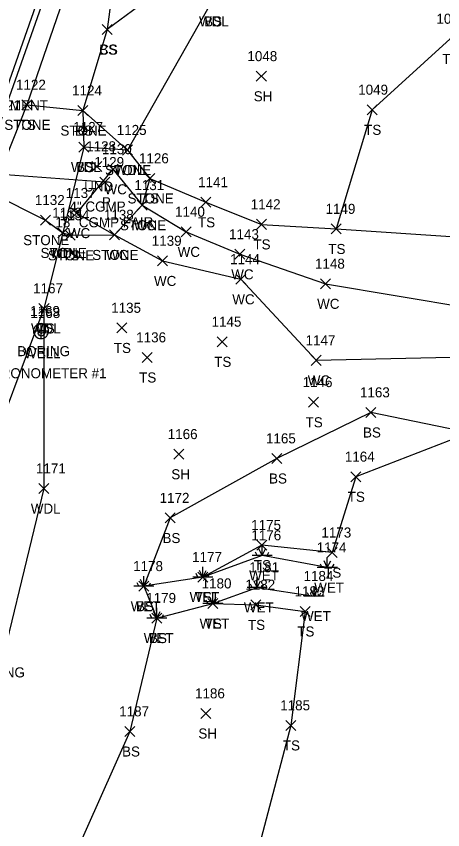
# Model space of a CAD drawing. Extents: x 1551995 to 1555700, y 777276 to 783130.
# Drawn here: x 1554961.7 to 1555046.7, y 777956 to 778118.1 of the extents above; entities that cross this region are included whole.
import ezdxf

# ---------------------------------------------------------------- set-up
doc = ezdxf.new("R2010")
doc.units = 0
for name, color, linetype in [('D_A', 7, 'Continuous'), ('D_C', 7, 'Continuous'), ('D_I', 7, 'Continuous'), ('D_TIC', 7, 'Continuous'), ('DCP', 7, 'Continuous'), ('G_A', 7, 'Continuous'), ('G_I', 7, 'Continuous'), ('GA_P', 7, 'Continuous'), ('L_A', 7, 'Continuous'), ('L_C', 7, 'Continuous'), ('L_I', 7, 'Continuous'), ('L_TIC', 7, 'Continuous'), ('LASF', 7, 'Continuous'), ('LAWA', 7, 'Continuous'), ('LAWE', 7, 'Continuous'), ('LELB', 7, 'Continuous'), ('LWET', 7, 'Continuous'), ('PET', 7, 'Continuous'), ('R_I', 7, 'Continuous'), ('RGR', 7, 'Continuous'), ('U_A', 7, 'Continuous'), ('U_C', 7, 'Continuous'), ('U_I', 7, 'Continuous'), ('UWW', 7, 'Continuous')]:
    doc.layers.add(name, color=color, linetype=linetype)

msp = doc.modelspace()

# ---------------------------------------------------------------- linework, layer by layer
at = {"layer": 'D_TIC'}
for points in [[(1554976.76, 778087.18), (1554978.76, 778089.18)], [(1554978.76, 778087.18), (1554976.76, 778089.18)], [(1554978.38, 778084.04), (1554980.38, 778086.04)], [(1554980.38, 778084.04), (1554978.38, 778086.04)]]:
    msp.add_lwpolyline(points, dxfattribs=at)
at = {"layer": 'DCP'}
msp.add_lwpolyline([(1554979.38, 778085.04), (1554918.24, 778089.56)], dxfattribs=at)
at = {"layer": 'GA_P'}
for p, q in [((1554966.63, 778055.36), (1554966.63, 778056.86)), ((1554966.63, 778055.36), (1554965.13, 778055.36)), ((1554968.13, 778055.36), (1554966.63, 778055.36)), ((1554966.63, 778053.86), (1554966.63, 778055.36))]:
    msp.add_line(p, q, dxfattribs=at)
for start, end in [(90, 180), (0, 90), (180, 270), (270, 0)]:
    msp.add_arc((1554966.63, 778055.36), 1.5, start, end, dxfattribs=at)
at = {"layer": 'L_TIC'}
for points in [[(1554978.79, 778114.45), (1554980.79, 778116.45)], [(1554980.79, 778114.45), (1554978.79, 778116.45)], [(1554978.79, 778114.45), (1554980.79, 778116.45)], [(1554980.79, 778114.45), (1554978.79, 778116.45)], [(1555009.56, 778105.15), (1555011.56, 778107.15)], [(1555011.56, 778105.15), (1555009.56, 778107.15)], [(1554962.77, 778099.46), (1554964.77, 778101.46)], [(1554964.77, 778099.46), (1554962.77, 778101.46)], [(1554962.77, 778099.46), (1554964.77, 778101.46)], [(1554964.77, 778099.46), (1554962.77, 778101.46)], [(1554962.77, 778099.46), (1554964.77, 778101.46)], [(1554964.77, 778099.46), (1554962.77, 778101.46)], [(1554973.95, 778098.31), (1554975.95, 778100.31)], [(1554975.95, 778098.31), (1554973.95, 778100.31)], [(1554973.95, 778098.31), (1554975.95, 778100.31)], [(1554975.95, 778098.31), (1554973.95, 778100.31)], [(1555031.66, 778098.46), (1555033.66, 778100.46)], [(1555033.66, 778098.46), (1555031.66, 778100.46)], [(1554974.19, 778091.03), (1554976.19, 778093.03)], [(1554976.19, 778091.03), (1554974.19, 778093.03)], [(1554974.19, 778091.03), (1554976.19, 778093.03)], [(1554976.19, 778091.03), (1554974.19, 778093.03)], [(1554982.85, 778090.44), (1554984.85, 778092.44)], [(1554984.85, 778090.44), (1554982.85, 778092.44)], [(1554982.85, 778090.44), (1554984.85, 778092.44)], [(1554984.85, 778090.44), (1554982.85, 778092.44)], [(1554979.98, 778086.61), (1554981.98, 778088.61)], [(1554981.98, 778086.61), (1554979.98, 778088.61)], [(1554979.98, 778086.61), (1554981.98, 778088.61)], [(1554981.98, 778086.61), (1554979.98, 778088.61)], [(1554987.34, 778084.79), (1554989.34, 778086.79)], [(1554989.34, 778084.79), (1554987.34, 778086.79)], [(1554987.34, 778084.79), (1554989.34, 778086.79)], [(1554989.34, 778084.79), (1554987.34, 778086.79)], [(1554985.81, 778079.45), (1554987.81, 778081.45)], [(1554987.81, 778079.45), (1554985.81, 778081.45)], [(1554985.81, 778079.45), (1554987.81, 778081.45)], [(1554987.81, 778079.45), (1554985.81, 778081.45)], [(1554998.52, 778080.03), (1555000.52, 778082.03)], [(1555000.52, 778080.03), (1554998.52, 778082.03)], [(1554972.68, 778077.88), (1554974.68, 778079.88)], [(1554974.68, 778077.88), (1554972.68, 778079.88)], [(1554966.53, 778076.48), (1554968.53, 778078.48)], [(1554968.53, 778076.48), (1554966.53, 778078.48)], [(1555009.57, 778075.63), (1555011.57, 778077.63)], [(1555011.57, 778075.63), (1555009.57, 778077.63)], [(1554969.99, 778073.93), (1554971.99, 778075.93)], [(1554971.99, 778073.93), (1554969.99, 778075.93)], [(1554969.99, 778073.93), (1554971.99, 778075.93)], [(1554971.99, 778073.93), (1554969.99, 778075.93)], [(1554994.57, 778074.14), (1554996.57, 778076.14)], [(1554996.57, 778074.14), (1554994.57, 778076.14)], [(1555024.51, 778074.72), (1555026.51, 778076.72)], [(1555026.51, 778074.72), (1555024.51, 778076.72)], [(1555024.51, 778074.72), (1555026.51, 778076.72)], [(1555026.51, 778074.72), (1555024.51, 778076.72)], [(1554971.46, 778073.45), (1554973.46, 778075.45)], [(1554973.46, 778073.45), (1554971.46, 778075.45)], [(1554971.46, 778073.45), (1554973.46, 778075.45)], [(1554973.46, 778073.45), (1554971.46, 778075.45)], [(1554980.3, 778073.53), (1554982.3, 778075.53)], [(1554982.3, 778073.53), (1554980.3, 778075.53)], [(1554980.3, 778073.53), (1554982.3, 778075.53)], [(1554982.3, 778073.53), (1554980.3, 778075.53)], [(1554980.3, 778073.53), (1554982.3, 778075.53)], [(1554982.3, 778073.53), (1554980.3, 778075.53)], [(1555005.25, 778069.66), (1555007.25, 778071.66)], [(1555007.25, 778069.66), (1555005.25, 778071.66)], [(1554989.85, 778068.35), (1554991.85, 778070.35)], [(1554991.85, 778068.35), (1554989.85, 778070.35)], [(1555005.46, 778064.69), (1555007.46, 778066.69)], [(1555007.46, 778064.69), (1555005.46, 778066.69)], [(1555022.38, 778063.79), (1555024.38, 778065.79)], [(1555024.38, 778063.79), (1555022.38, 778065.79)], [(1554966.22, 778058.88), (1554968.22, 778060.88)], [(1554968.22, 778058.88), (1554966.22, 778060.88)], [(1554966.22, 778058.88), (1554968.22, 778060.88)], [(1554968.22, 778058.88), (1554966.22, 778060.88)], [(1554981.74, 778055), (1554983.74, 778057)], [(1554983.74, 778055), (1554981.74, 778057)], [(1555001.76, 778052.23), (1555003.76, 778054.23)], [(1555003.76, 778052.23), (1555001.76, 778054.23)], [(1554986.79, 778049.11), (1554988.79, 778051.11)], [(1554988.79, 778049.11), (1554986.79, 778051.11)], [(1555020.52, 778048.53), (1555022.52, 778050.53)], [(1555022.52, 778048.53), (1555020.52, 778050.53)], [(1555019.98, 778040.19), (1555021.98, 778042.19)], [(1555021.98, 778040.19), (1555019.98, 778042.19)], [(1555031.4, 778038.15), (1555033.4, 778040.15)], [(1555033.4, 778038.15), (1555031.4, 778040.15)], [(1554993.13, 778029.83), (1554995.13, 778031.83)], [(1554995.13, 778029.83), (1554993.13, 778031.83)], [(1555012.66, 778028.98), (1555014.66, 778030.98)], [(1555014.66, 778028.98), (1555012.66, 778030.98)], [(1555028.38, 778025.34), (1555030.38, 778027.34)], [(1555030.38, 778025.34), (1555028.38, 778027.34)], [(1554966.17, 778022.98), (1554968.17, 778024.98)], [(1554968.17, 778022.98), (1554966.17, 778024.98)], [(1554991.41, 778017.12), (1554993.41, 778019.12)], [(1554993.41, 778017.12), (1554991.41, 778019.12)], [(1555009.67, 778011.71), (1555011.67, 778013.71)], [(1555011.67, 778011.71), (1555009.67, 778013.71)], [(1555023.68, 778010.22), (1555025.68, 778012.22)], [(1555025.68, 778010.22), (1555023.68, 778012.22)], [(1554997.88, 778005.35), (1554999.88, 778007.35)], [(1554999.88, 778005.35), (1554997.88, 778007.35)], [(1554986.13, 778003.53), (1554988.13, 778005.53)], [(1554988.13, 778003.53), (1554986.13, 778005.53)], [(1554999.87, 778000.08), (1555001.87, 778002.08)], [(1555001.87, 778000.08), (1554999.87, 778002.08)], [(1555008.49, 777999.82), (1555010.49, 778001.82)], [(1555010.49, 777999.82), (1555008.49, 778001.82)], [(1555018.32, 777998.5), (1555020.32, 778000.5)], [(1555020.32, 777998.5), (1555018.32, 778000.5)], [(1554988.73, 777997.18), (1554990.73, 777999.18)], [(1554990.73, 777997.18), (1554988.73, 777999.18)], [(1554998.52, 777978.17), (1555000.52, 777980.17)], [(1555000.52, 777978.17), (1554998.52, 777980.17)], [(1555015.45, 777975.79), (1555017.45, 777977.79)], [(1555017.45, 777975.79), (1555015.45, 777977.79)], [(1554983.34, 777974.58), (1554985.34, 777976.58)], [(1554985.34, 777974.58), (1554983.34, 777976.58)]]:
    msp.add_lwpolyline(points, dxfattribs=at)
at = {"layer": 'LASF'}
for points in [[(1554963.77, 778100.46), (1554956.78, 778082.85), (1554967.53, 778077.48), (1554970.99, 778074.93), (1554972.46, 778074.45), (1554981.3, 778074.53)], [(1554963.77, 778100.46), (1554974.95, 778099.31), (1554983.85, 778091.44), (1554988.34, 778085.79), (1554986.81, 778080.45), (1554981.3, 778074.53)]]:
    msp.add_lwpolyline(points, dxfattribs=at)
at = {"layer": 'LAWA'}
msp.add_lwpolyline([(1555085.12, 778246.6), (1555062.11, 778217.51), (1555036.75, 778197.89), (1555030.02, 778178.79), (1555023.09, 778154.13), (1555005.22, 778133.85), (1555000.72, 778121.06), (1554983.85, 778091.44), (1554975.19, 778092.03), (1554970.99, 778074.93), (1554967.22, 778059.88), (1554967.17, 778023.98), (1554956.28, 777979.25), (1554949.24, 777950.5), (1554942.15, 777917.97), (1554937.88, 777884.35), (1554924.17, 777845.95), (1554911.99, 777797.39)], dxfattribs=at)
at = {"layer": 'LAWE'}
for points in [[(1554980.98, 778087.61), (1554986.81, 778080.45), (1554995.57, 778075.14), (1555006.25, 778070.66), (1555023.38, 778064.79), (1555066.22, 778057.61), (1555079.37, 778049.92), (1555092.5, 778039.7), (1555103.43, 778032.31), (1555111.16, 778025.28), (1555121.81, 778022.05), (1555131.79, 778023.3), (1555142.1, 778032.9), (1555159.88, 778037.39), (1555175.92, 778041.48), (1555190.31, 778048.94), (1555221.06, 778078.31), (1555223.43, 778108.97), (1555239.75, 778121.69), (1555250.77, 778129.37)], [(1554980.98, 778087.61), (1554973.68, 778078.88), (1554981.3, 778074.53), (1554990.85, 778069.35), (1555006.46, 778065.69), (1555021.52, 778049.53), (1555063.27, 778050.47), (1555075.24, 778046.42)]]:
    msp.add_lwpolyline(points, dxfattribs=at)
at = {"layer": 'LELB'}
for points in [[(1555043.36, 778265.96), (1555018.33, 778220.45), (1555000.7, 778188.06), (1554983.47, 778153.1), (1554971.68, 778123.43), (1554963.77, 778100.46)], [(1555062.53, 778257.03), (1555043.05, 778221.53), (1555026.82, 778208.44), (1555019.74, 778198.68), (1555014.58, 778191.04), (1555012.64, 778162.24), (1554995.57, 778139.61), (1554992.44, 778124.79), (1554979.79, 778115.45), (1554974.95, 778099.31), (1554975.19, 778092.03)], [(1555014.58, 778191.04), (1555000.34, 778164.05), (1554987.94, 778141.56), (1554981.54, 778128.64), (1554979.79, 778115.45)], [(1555030.02, 778178.79), (1555043.74, 778160.89), (1555054.04, 778147.86), (1555060.5, 778139.33), (1555048.25, 778113.6), (1555032.66, 778099.46), (1555025.51, 778075.72)], [(1554988.34, 778085.79), (1554999.52, 778081.03), (1555010.57, 778076.63), (1555025.51, 778075.72), (1555050.35, 778074.06), (1555071.47, 778069.38), (1555082.88, 778057.69), (1555090.96, 778044.64), (1555104.92, 778035.73), (1555112.51, 778027.47), (1555122.17, 778023.62), (1555130.48, 778025.48), (1555140.65, 778033.87), (1555161.85, 778040.13), (1555175.62, 778046.97), (1555180.05, 778050.72)], [(1554967.22, 778059.88), (1554954.84, 778026.93)], [(1555055.12, 778044.08), (1555052.07, 778035.1), (1555029.38, 778026.34), (1555024.68, 778011.22), (1555010.67, 778012.71), (1554998.88, 778006.35)], [(1555052.07, 778035.1), (1555032.4, 778039.15), (1555013.66, 778029.98), (1554992.41, 778018.12), (1554987.13, 778004.53)], [(1555000.87, 778001.08), (1555009.49, 778000.82), (1555019.32, 777999.5), (1555016.45, 777976.79), (1555007.25, 777941.96), (1555001.69, 777908.63), (1554997.48, 777871.9), (1554988.59, 777829.9), (1554987.68, 777801.59), (1554990.67, 777771.72), (1554987.39, 777735.48), (1554982.18, 777719.34), (1554965.91, 777692.12), (1554960.8, 777672.01)], [(1554989.73, 777998.18), (1554984.34, 777975.58), (1554972.66, 777949.31), (1554962.52, 777914.84), (1554954.2, 777880.1), (1554942.29, 777842.69), (1554932.5, 777796.7), (1554925.54, 777781.17), (1554929.46, 777763.36)]]:
    msp.add_lwpolyline(points, dxfattribs=at)
at = {"layer": 'LWET'}
for p, q in [((1555010.75, 778010.67), (1555010.75, 778012.67)), ((1555009.75, 778010.67), (1555009.42, 778011.33)), ((1555010.75, 778010.67), (1555010.09, 778012)), ((1555010.75, 778010.67), (1555011.42, 778012)), ((1555011.75, 778010.67), (1555012.09, 778011.33)), ((1555012.75, 778010.67), (1555008.75, 778010.67)), ((1555023.72, 778008.24), (1555023.06, 778009.57)), ((1555023.72, 778008.24), (1555023.72, 778010.24)), ((1555023.72, 778008.24), (1555024.39, 778009.57)), ((1554998.88, 778006.35), (1554998.22, 778007.68)), ((1554998.88, 778006.35), (1554998.88, 778008.35)), ((1554998.88, 778006.35), (1554999.55, 778007.68)), ((1555025.72, 778008.24), (1555021.72, 778008.24)), ((1555022.72, 778008.24), (1555022.39, 778008.9)), ((1555024.72, 778008.24), (1555025.06, 778008.9)), ((1554987.13, 778004.53), (1554987.13, 778006.53)), ((1555000.88, 778006.35), (1554996.88, 778006.35)), ((1554997.88, 778006.35), (1554997.55, 778007.02)), ((1554999.88, 778006.35), (1555000.22, 778007.02)), ((1555009.71, 778004.29), (1555009.71, 778006.29)), ((1554989.13, 778004.53), (1554985.13, 778004.53)), ((1554986.13, 778004.53), (1554985.8, 778005.2)), ((1554987.13, 778004.53), (1554986.46, 778005.87)), ((1554987.13, 778004.53), (1554987.8, 778005.87)), ((1554988.13, 778004.53), (1554988.46, 778005.2)), ((1555008.71, 778004.29), (1555008.37, 778004.96)), ((1555009.71, 778004.29), (1555009.04, 778005.62)), ((1555009.71, 778004.29), (1555010.37, 778005.62)), ((1555010.71, 778004.29), (1555011.04, 778004.96)), ((1555021.11, 778002.56), (1555021.11, 778004.56)), ((1555000.87, 778001.08), (1555000.87, 778003.08)), ((1555011.71, 778004.29), (1555007.71, 778004.29)), ((1555020.11, 778002.56), (1555019.77, 778003.23)), ((1555021.11, 778002.56), (1555020.44, 778003.9)), ((1555021.11, 778002.56), (1555021.77, 778003.9)), ((1555022.11, 778002.56), (1555022.44, 778003.23)), ((1555002.87, 778001.08), (1554998.87, 778001.08)), ((1554999.87, 778001.08), (1554999.54, 778001.75)), ((1555000.87, 778001.08), (1555000.2, 778002.42)), ((1555000.87, 778001.08), (1555001.54, 778002.42)), ((1555001.87, 778001.08), (1555002.2, 778001.75)), ((1555023.11, 778002.56), (1555019.11, 778002.56)), ((1554989.73, 777998.18), (1554989.07, 777999.51)), ((1554989.73, 777998.18), (1554989.73, 778000.18)), ((1554989.73, 777998.18), (1554990.4, 777999.51)), ((1554991.73, 777998.18), (1554987.73, 777998.18)), ((1554988.73, 777998.18), (1554988.4, 777998.85)), ((1554990.73, 777998.18), (1554991.07, 777998.85))]:
    msp.add_line(p, q, dxfattribs=at)
msp.add_lwpolyline([(1555023.72, 778008.24), (1555010.75, 778010.67), (1554998.88, 778006.35), (1554987.13, 778004.53), (1554989.73, 777998.18), (1555000.87, 778001.08), (1555009.71, 778004.29), (1555021.11, 778002.56)], dxfattribs=at)
at = {"layer": 'PET'}
msp.add_lwpolyline([(1555108.52, 778369.81), (1555078.86, 778330.23), (1555056.92, 778298.28), (1555038.33, 778268.72), (1555013, 778223.52), (1554996, 778190.4), (1554978.91, 778154.53), (1554967.24, 778125.11), (1554957.25, 778096.67), (1554950.17, 778073.38), (1554937.06, 778028.22), (1554926.8, 777988.52), (1554918.72, 777954.59), (1554908.46, 777910.08), (1554899.75, 777869.14), (1554889.9, 777822.39), (1554877.4, 777767.74)], dxfattribs=at)
at = {"layer": 'RGR'}
msp.add_lwpolyline([(1555039.56, 778268.3), (1555013.62, 778223), (1554996.63, 778189.88), (1554979.88, 778154.08), (1554968.24, 778124.65), (1554958.2, 778096.32), (1554950.97, 778072.94), (1554937.27, 778027.95), (1554927.65, 777988.1), (1554919.66, 777954.37), (1554909.72, 777910.11), (1554900.5, 777868.18), (1554890.69, 777822.54), (1554878.36, 777767.59), (1554870.52, 777731.32), (1554860.9, 777689.38), (1554849.55, 777645.14), (1554835.81, 777600.33), (1554822.79, 777564.15), (1554817.07, 777548.72), (1554816.7, 777536.06)], dxfattribs=at)
at = {"layer": 'UWW'}
for radius in [0.625, 0.0833]:
    msp.add_circle((1554966.69, 778054.96), radius, dxfattribs=at)

# ---------------------------------------------------------------- texts
at = {"layer": 'D_A'}
for s, p in [('UND', (1554975.23, 778083.18)), ('P', (1554978.76, 778080.04))]:
    msp.add_text(s, height=2, dxfattribs=at).set_placement(p)
at = {"layer": 'D_C'}
for s, p in [('4" CGMP', (1554972.3, 778079.18)), ('18" CGMP FAIR', (1554969.5, 778076.04))]:
    msp.add_text(s, height=2, dxfattribs=at).set_placement(p)
at = {"layer": 'D_I'}
for s, p in [('1128', (1554975.63, 778091.18)), ('1129', (1554977.25, 778088.04))]:
    msp.add_text(s, height=2, dxfattribs=at).set_placement(p)
at = {"layer": 'G_A'}
for p in [(1554961.87, 778050.36), (1554952.86, 777986.35)]:
    msp.add_text('BORING', height=2, dxfattribs=at).set_placement(p)
at = {"layer": 'G_I'}
msp.add_text('1169', height=2, dxfattribs=at).set_placement((1554964.45, 778058.36))
at = {"layer": 'L_A'}
for s, p in [('WDL', (1554998.14, 778116.06)), ('BS', (1554999.16, 778116.06)), ('CS', (1554978.23, 778110.45)), ('BS', (1554978.23, 778110.45)), ('TS', (1555046.66, 778108.6)), ('SH', (1555009.05, 778101.15)), ('STONE', (1554959.31, 778095.46)), ('STONE', (1554959.31, 778095.46)), ('TS', (1554962.18, 778095.46)), ('STONE', (1554970.5, 778094.31)), ('BS', (1554973.4, 778094.31)), ('TS', (1555031.07, 778094.46)), ('WDL', (1554972.6, 778087.03)), ('BS', (1554973.63, 778087.03)), ('STONE', (1554979.4, 778086.44)), ('WDL', (1554981.27, 778086.44)), ('WC', (1554979.29, 778082.61)), ('WC', (1554979.29, 778082.61)), ('STONE', (1554983.88, 778080.79)), ('TS', (1554986.75, 778080.79)), ('STONE', (1554982.36, 778075.45)), ('WC', (1554985.12, 778075.45)), ('TS', (1554997.93, 778076.03)), ('WC', (1554971.99, 778073.88)), ('STONE', (1554963.07, 778072.48)), ('TS', (1555008.98, 778071.63)), ('TS', (1555023.92, 778070.72)), ('TS', (1555023.92, 778070.72)), ('STONE', (1554966.53, 778069.93)), ('STONE', (1554968, 778069.45)), ('WDL', (1554968.4, 778069.93)), ('TS', (1554970.87, 778069.45)), ('STONE', (1554976.84, 778069.53)), ('STONE', (1554976.84, 778069.53)), ('WC', (1554979.6, 778069.53)), ('WC', (1554993.88, 778070.14)), ('WC', (1555004.56, 778065.66)), ('WC', (1554989.16, 778064.35)), ('WC', (1555004.77, 778060.69)), ('WC', (1555021.69, 778059.79)), ('WDL', (1554964.64, 778054.88)), ('CS', (1554965.66, 778054.88)), ('TS', (1554981.15, 778051)), ('TS', (1555001.17, 778048.23)), ('TS', (1554986.2, 778045.11)), ('WC', (1555019.82, 778044.53)), ('TS', (1555019.39, 778036.19)), ('BS', (1555030.84, 778034.15)), ('SH', (1554992.61, 778025.83)), ('BS', (1555012.1, 778024.98)), ('TS', (1555027.79, 778021.34)), ('WDL', (1554964.59, 778018.98)), ('BS', (1554990.85, 778013.12)), ('TS', (1555009.07, 778007.71)), ('WET', (1555008.13, 778005.67)), ('TS', (1555023.09, 778006.22)), ('WET', (1555021.1, 778003.24)), ('WET', (1554996.26, 778001.35)), ('TS', (1554997.29, 778001.35)), ('WET', (1554984.51, 777999.53)), ('BS', (1554985.57, 777999.53)), ('WET', (1555007.08, 777999.29)), ('WET', (1555018.48, 777997.56)), ('WET', (1554998.25, 777996.08)), ('TS', (1554999.28, 777996.08)), ('TS', (1555007.9, 777995.82)), ('TS', (1555017.73, 777994.5)), ('WET', (1554987.11, 777993.18)), ('BS', (1554988.17, 777993.18)), ('SH', (1554998.01, 777974.17)), ('TS', (1555014.86, 777971.79)), ('BS', (1554982.79, 777970.58))]:
    msp.add_text(s, height=2, dxfattribs=at).set_placement(p)
at = {"layer": 'L_C'}
msp.add_text('CRACK IN PAVEMENT', height=2, dxfattribs=at).set_placement((1554939.77, 778099.34))
at = {"layer": 'L_I'}
for s, p in [('1034', (1555045.48, 778116.6)), ('1048', (1555007.79, 778109.15)), ('1122', (1554961.64, 778103.46)), ('1122', (1554961.64, 778103.46)), ('1122', (1554961.64, 778103.46)), ('1124', (1554972.83, 778102.31)), ('1124', (1554972.83, 778102.31)), ('1049', (1555029.88, 778102.46)), ('1127', (1554973.06, 778095.03)), ('1127', (1554973.06, 778095.03)), ('1125', (1554981.73, 778094.44)), ('1125', (1554981.73, 778094.44)), ('1130', (1554978.77, 778090.61)), ('1130', (1554978.77, 778090.61)), ('1126', (1554986.16, 778088.79)), ('1126', (1554986.16, 778088.79)), ('1131', (1554985.25, 778083.45)), ('1131', (1554985.25, 778083.45)), ('1141', (1554997.96, 778084.03)), ('1137', (1554971.56, 778081.88)), ('1132', (1554965.4, 778080.48)), ('1142', (1555008.45, 778079.63)), ('1149', (1555023.37, 778078.72)), ('1149', (1555023.37, 778078.72)), ('1133', (1554968.86, 778077.93)), ('1133', (1554968.86, 778077.93)), ('1134', (1554970.33, 778077.45)), ('1134', (1554970.33, 778077.45)), ('1138', (1554979.17, 778077.53)), ('1138', (1554979.17, 778077.53)), ('1138', (1554979.17, 778077.53)), ('1140', (1554993.36, 778078.14)), ('1143', (1555004.13, 778073.66)), ('1139', (1554988.71, 778072.35)), ('1144', (1555004.34, 778068.69)), ('1148', (1555021.26, 778067.79)), ('1167', (1554965.05, 778062.88)), ('1167', (1554965.05, 778062.88)), ('1135', (1554980.62, 778059)), ('1145', (1555000.64, 778056.23)), ('1136', (1554985.61, 778053.11)), ('1147', (1555019.39, 778052.53)), ('1146', (1555018.8, 778044.19)), ('1163', (1555030.23, 778042.15)), ('1166', (1554991.9, 778033.83)), ('1165', (1555011.49, 778032.98)), ('1164', (1555027.21, 778029.34)), ('1171', (1554965.61, 778026.98)), ('1172', (1554990.28, 778021.12)), ('1175', (1555008.54, 778015.71)), ('1176', (1555008.57, 778013.67)), ('1173', (1555022.55, 778014.22)), ('1174', (1555021.6, 778011.24)), ('1177', (1554996.76, 778009.35)), ('1177', (1554996.76, 778009.35)), ('1178', (1554985, 778007.53)), ('1178', (1554985, 778007.53)), ('1181', (1555008.15, 778007.29)), ('1184', (1555018.98, 778005.56)), ('1180', (1554998.66, 778004.08)), ('1180', (1554998.66, 778004.08)), ('1182', (1555007.37, 778003.82)), ('1183', (1555017.19, 778002.5)), ('1179', (1554987.6, 778001.18)), ('1179', (1554987.6, 778001.18)), ('1186', (1554997.34, 777982.17)), ('1185', (1555014.33, 777979.79)), ('1187', (1554982.22, 777978.58))]:
    msp.add_text(s, height=2, dxfattribs=at).set_placement(p)
at = {"layer": 'R_I'}
msp.add_text('1121', height=2, dxfattribs=at).set_placement((1554956.64, 778099.32))
at = {"layer": 'U_A'}
msp.add_text('WELL', height=2, dxfattribs=at).set_placement((1554963.25, 778049.96))
at = {"layer": 'U_C'}
msp.add_text('INCRONOMETER #1', height=2, dxfattribs=at).set_placement((1554953.99, 778045.96))
at = {"layer": 'U_I'}
msp.add_text('1168', height=2, dxfattribs=at).set_placement((1554964.51, 778057.96))

doc.saveas('drawing.dxf')
